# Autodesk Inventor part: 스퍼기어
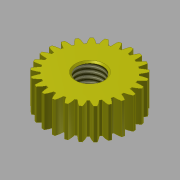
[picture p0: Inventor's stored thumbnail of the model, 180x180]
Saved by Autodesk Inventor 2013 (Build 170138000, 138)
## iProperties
Created: 2017-04
Part Number: 스퍼기어
Material: 강철
Document SubType Name: Modeling
Designer: mduedu
Categories: <?xml version="1.0" encoding="UTF-16"?> <MemberInstance><Categories><FamilyTemplate><FamilyTemplateParameter ValueType="xs:double" Id="1" ObjectReferenceKey="da
Density: 7.85 g/cm^3
Mass: 32.0047 g
Surface Area: 26.9526 cm^2
Volume: 4.07703 cm^3
Author: mduedu
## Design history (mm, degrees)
sketch "Sketch1"
  geometry: C1 r 13.5 at (0, 0)
  constraints: 1 centre point
  dimensions: "d0" = 27 diameter of C1 (= da_da)
extrude "Extrusion1" new body sketch "Sketch1" distance "d1" = 10 (= da_b); taper "d2" = 0 deg
workplane "Work Plane2"
sketch "Sketch2"
  geometry: C1 r 13.5 at (0, 0) reference; C2 r 12.5 at (0, 0)
  constraints: 1 centre point, 1 coincident
  dimensions: "d3" = 25 diameter of C2 (= da_dw)
feature "피치 지름" sketch "Sketch2" dims "d4" = 10, "d5" = 0
workplane "Work Plane8"
workplane "Work Plane9"
feature "스퍼 기어" dims "da_b" = 10, "da_d" = 25, "da_aw" = 25, "da_da" = 27, "da_df" = 22.5, "da_dw" = 25, angle "da_beta" = 0 deg, "da_lefttooth" = 0, "da_righttooth" = 0
sketch "스케치3"
  geometry: C1 r 4.188 at (0, 0); 1 further point
  constraints: 1 centre point, 1 coincident
  dimensions: "d49" = 8.376 diameter of C1
extrude "돌출2" cut sketch "스케치3" stored distance "d50" = 10; taper "d51" = 0 deg
feature "스레드1" dims "d52" = 10, "d53" = 0
chamfer "모따기1" distance "d54" = 0.5; stored, may be unused: second distance "d55" = 2, angle "d56" = 45 deg
body "Solid1"
body "Srf1"
other parameters: "d16" = 25 (= da_aw), "d17" = 0, "d34" = 1.25664 (computed from da_z), "d39" = 0, "d41" = 0, "d43" = 25 (= da_aw), "d46" = 25 (= da_aw), "d47" = 0, "d48" = 0
